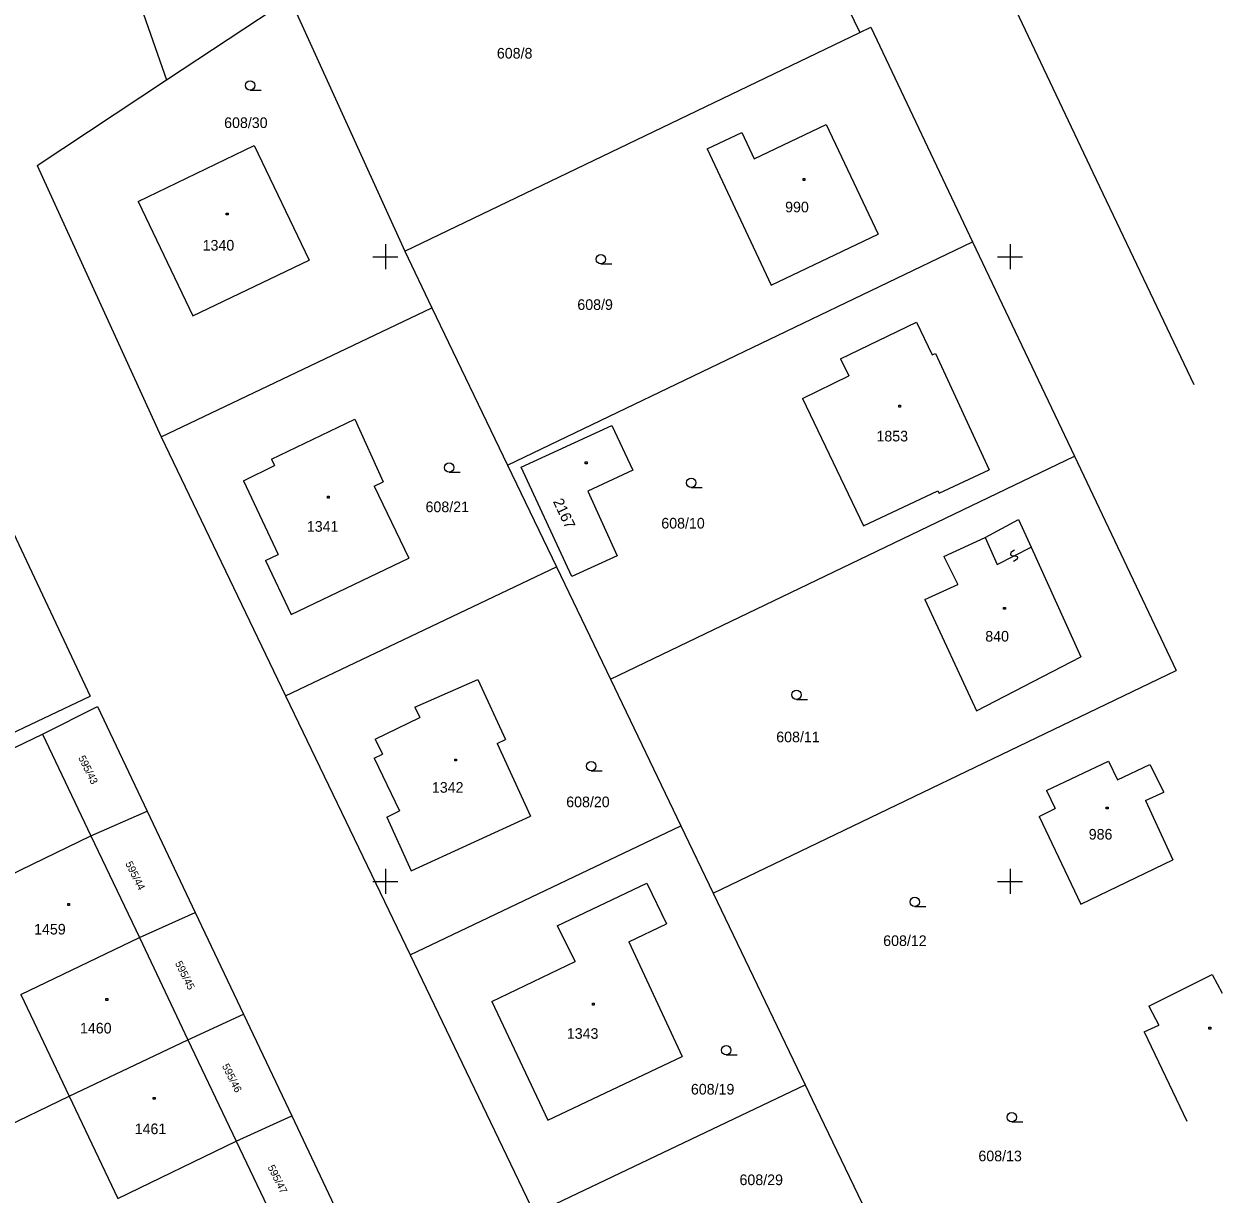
# Model space of a CAD drawing. Extents: x -493648 to -493033, y -1127718 to -1127026.
# Drawn here: x -493128.9 to -493033, y -1127275 to -1127181.4 of the extents above; entities that cross this region are included whole.
import ezdxf

# ---------------------------------------------------------------- set-up
doc = ezdxf.new("R2010")
doc.units = 0
doc.layers.add('katastrální mapa', color=7, linetype='Continuous')
doc.layers.add('síť', color=7, linetype='Continuous')

msp = doc.modelspace()

# ---------------------------------------------------------------- linework, layer by layer
at = {"layer": 'katastrální mapa'}
for p, q in [((-493063.68, -1127150.51), (-493043.37, -1127193.26)), ((-493073.86, -1127157.16), (-493062.04, -1127182.05)), ((-493117.52, -1127185.82), (-493107.66, -1127179.29)), ((-493107.66, -1127179.29), (-493098.45, -1127199.56)), ((-493119.75, -1127179.52), (-493117.52, -1127185.82)), ((-493098.45, -1127199.56), (-493062.04, -1127182.05)), ((-493062.04, -1127182.05), (-493061.14, -1127181.62)), ((-493061.14, -1127181.62), (-493053, -1127198.79)), ((-493127.87, -1127192.68), (-493117.52, -1127185.82)), ((-493110.83, -1127186.65), (-493109.95, -1127186.65)), ((-493070.48, -1127192.15), (-493064.72, -1127189.41)), ((-493064.72, -1127189.41), (-493060.57, -1127198.19)), ((-493074.24, -1127191.36), (-493071.48, -1127190.05)), ((-493071.48, -1127190.05), (-493070.48, -1127192.15)), ((-493119.79, -1127195.56), (-493110.5, -1127191.08)), ((-493110.5, -1127191.08), (-493106.11, -1127200.27)), ((-493074.24, -1127191.36), (-493069.14, -1127202.26)), ((-493127.87, -1127192.68), (-493117.94, -1127214.4)), ((-493066.57, -1127193.73), (-493066.42, -1127193.73)), ((-493066.57, -1127193.88), (-493066.57, -1127193.73)), ((-493066.42, -1127193.73), (-493066.42, -1127193.88)), ((-493043.37, -1127193.26), (-493035.31, -1127210.23)), ((-493066.42, -1127193.88), (-493066.57, -1127193.88)), ((-493119.79, -1127195.56), (-493115.41, -1127204.72)), ((-493112.75, -1127196.5), (-493112.6, -1127196.5)), ((-493112.75, -1127196.65), (-493112.75, -1127196.5)), ((-493112.6, -1127196.65), (-493112.75, -1127196.65)), ((-493112.6, -1127196.5), (-493112.6, -1127196.65)), ((-493069.14, -1127202.26), (-493060.57, -1127198.19)), ((-493098.45, -1127199.56), (-493096.28, -1127204.09)), ((-493090.22, -1127216.69), (-493053, -1127198.79)), ((-493053, -1127198.79), (-493044.86, -1127215.96)), ((-493115.41, -1127204.72), (-493106.11, -1127200.27)), ((-493082.76, -1127200.57), (-493081.88, -1127200.57)), ((-493117.94, -1127214.4), (-493096.28, -1127204.09)), ((-493096.28, -1127204.09), (-493090.22, -1127216.69)), ((-493063.58, -1127208.18), (-493057.5, -1127205.23)), ((-493057.5, -1127205.23), (-493056.23, -1127207.84)), ((-493063.58, -1127208.18), (-493062.92, -1127209.54)), ((-493056.23, -1127207.84), (-493055.98, -1127207.73)), ((-493055.98, -1127207.73), (-493051.67, -1127217.06)), ((-493066.61, -1127211.33), (-493062.92, -1127209.54)), ((-493066.61, -1127211.33), (-493061.74, -1127221.53)), ((-493058.92, -1127211.88), (-493058.77, -1127211.88)), ((-493058.92, -1127212.03), (-493058.92, -1127211.88)), ((-493058.77, -1127212.03), (-493058.92, -1127212.03)), ((-493058.77, -1127211.88), (-493058.77, -1127212.03)), ((-493109.11, -1127216.2), (-493102.45, -1127212.99)), ((-493102.45, -1127212.99), (-493100.17, -1127218.01)), ((-493133.79, -1127213.61), (-493123.64, -1127235.17)), ((-493089.13, -1127216.83), (-493081.89, -1127213.5)), ((-493081.89, -1127213.5), (-493080.2, -1127217.08)), ((-493117.94, -1127214.4), (-493107.99, -1127235.14)), ((-493111.35, -1127217.94), (-493108.88, -1127216.7)), ((-493109.11, -1127216.2), (-493108.88, -1127216.7)), ((-493090.22, -1127216.69), (-493086.32, -1127224.82)), ((-493085.07, -1127225.59), (-493089.13, -1127216.83)), ((-493084.01, -1127216.41), (-493083.86, -1127216.41)), ((-493084.01, -1127216.56), (-493084.01, -1127216.41)), ((-493083.86, -1127216.56), (-493084.01, -1127216.56)), ((-493083.86, -1127216.41), (-493083.86, -1127216.56)), ((-493082, -1127233.82), (-493044.86, -1127215.96)), ((-493044.86, -1127215.96), (-493036.72, -1127233.12)), ((-493094.9, -1127217.25), (-493094.02, -1127217.25)), ((-493080.2, -1127217.08), (-493083.79, -1127218.75)), ((-493055.69, -1127218.93), (-493051.67, -1127217.06)), ((-493111.35, -1127217.94), (-493108.58, -1127223.84)), ((-493100.89, -1127218.36), (-493100.17, -1127218.01)), ((-493100.89, -1127218.36), (-493098.13, -1127224.13)), ((-493083.79, -1127218.75), (-493081.44, -1127223.93)), ((-493075.52, -1127218.46), (-493074.64, -1127218.46)), ((-493061.74, -1127221.53), (-493055.78, -1127218.74)), ((-493055.78, -1127218.74), (-493055.69, -1127218.93)), ((-493104.65, -1127219.16), (-493104.5, -1127219.16)), ((-493104.65, -1127219.31), (-493104.65, -1127219.16)), ((-493104.5, -1127219.31), (-493104.65, -1127219.31)), ((-493104.5, -1127219.16), (-493104.5, -1127219.31)), ((-493051.99, -1127222.46), (-493049.34, -1127221.04)), ((-493049.34, -1127221.04), (-493048.33, -1127223.24)), ((-493055.3, -1127224), (-493051.99, -1127222.46)), ((-493051.99, -1127222.46), (-493051.05, -1127224.63)), ((-493051.05, -1127224.63), (-493048.33, -1127223.24)), ((-493049.65, -1127223.47), (-493049.94, -1127223.67)), ((-493048.33, -1127223.24), (-493044.33, -1127232.03)), ((-493109.61, -1127224.32), (-493108.58, -1127223.84)), ((-493109.61, -1127224.32), (-493107.55, -1127228.63)), ((-493107.55, -1127228.63), (-493098.13, -1127224.13)), ((-493081.44, -1127223.93), (-493085.07, -1127225.59)), ((-493055.3, -1127224), (-493054.18, -1127226.22)), ((-493049.94, -1127223.67), (-493049.98, -1127223.8)), ((-493049.98, -1127223.8), (-493049.94, -1127223.89)), ((-493049.94, -1127223.89), (-493049.8, -1127223.94)), ((-493049.8, -1127223.94), (-493049.58, -1127223.93)), ((-493049.44, -1127224.2), (-493049.73, -1127224.4)), ((-493049.58, -1127223.93), (-493049.44, -1127223.98)), ((-493049.44, -1127223.98), (-493049.4, -1127224.07)), ((-493049.4, -1127224.07), (-493049.44, -1127224.2)), ((-493107.99, -1127235.14), (-493086.32, -1127224.82)), ((-493086.32, -1127224.82), (-493082, -1127233.82)), ((-493056.84, -1127227.43), (-493054.18, -1127226.22)), ((-493056.84, -1127227.43), (-493052.69, -1127236.34)), ((-493050.52, -1127228.06), (-493050.37, -1127228.06)), ((-493050.52, -1127228.21), (-493050.52, -1127228.06)), ((-493050.37, -1127228.21), (-493050.52, -1127228.21)), ((-493050.37, -1127228.06), (-493050.37, -1127228.21)), ((-493052.69, -1127236.34), (-493044.33, -1127232.03)), ((-493073.78, -1127250.94), (-493036.72, -1127233.12)), ((-493097.66, -1127236.04), (-493092.6, -1127233.83)), ((-493092.6, -1127233.83), (-493090.39, -1127238.65)), ((-493082, -1127233.82), (-493076.37, -1127245.55)), ((-493131.12, -1127238.72), (-493123.64, -1127235.17)), ((-493127.44, -1127238.2), (-493123.05, -1127236.01)), ((-493123.05, -1127236.01), (-493119.08, -1127244.37)), ((-493107.99, -1127235.14), (-493098.03, -1127255.87)), ((-493067.1, -1127235.43), (-493066.22, -1127235.43)), ((-493100.82, -1127238.6), (-493097.25, -1127236.89)), ((-493097.66, -1127236.04), (-493097.25, -1127236.89)), ((-493131.56, -1127240.19), (-493127.44, -1127238.2)), ((-493127.44, -1127238.2), (-493123.57, -1127246.34)), ((-493100.82, -1127238.6), (-493100.24, -1127239.8)), ((-493091.05, -1127238.95), (-493090.39, -1127238.65)), ((-493100.91, -1127240.14), (-493100.24, -1127239.8)), ((-493091.05, -1127238.95), (-493088.38, -1127244.77)), ((-493100.91, -1127240.14), (-493098.88, -1127244.36)), ((-493094.45, -1127240.2), (-493094.3, -1127240.2)), ((-493094.45, -1127240.35), (-493094.45, -1127240.2)), ((-493094.3, -1127240.35), (-493094.45, -1127240.35)), ((-493094.3, -1127240.2), (-493094.3, -1127240.35)), ((-493047.09, -1127242.73), (-493042.13, -1127240.37)), ((-493042.13, -1127240.37), (-493041.41, -1127241.86)), ((-493041.41, -1127241.86), (-493038.83, -1127240.63)), ((-493038.83, -1127240.63), (-493037.7, -1127242.85)), ((-493083.53, -1127241.14), (-493082.65, -1127241.14)), ((-493047.09, -1127242.73), (-493046.4, -1127244.17)), ((-493039.16, -1127243.53), (-493037.7, -1127242.85)), ((-493039.16, -1127243.53), (-493036.97, -1127248.28)), ((-493123.57, -1127246.34), (-493119.08, -1127244.37)), ((-493119.08, -1127244.37), (-493115.22, -1127252.5)), ((-493099.89, -1127244.85), (-493098.88, -1127244.36)), ((-493047.69, -1127244.79), (-493046.4, -1127244.17)), ((-493042.31, -1127244.05), (-493042.16, -1127244.05)), ((-493042.31, -1127244.2), (-493042.31, -1127244.05)), ((-493042.16, -1127244.2), (-493042.31, -1127244.2)), ((-493042.16, -1127244.05), (-493042.16, -1127244.2)), ((-493099.89, -1127244.85), (-493097.93, -1127249.14)), ((-493098.03, -1127255.87), (-493076.37, -1127245.55)), ((-493097.93, -1127249.14), (-493088.38, -1127244.77)), ((-493076.37, -1127245.55), (-493073.78, -1127250.94)), ((-493047.69, -1127244.79), (-493044.33, -1127251.81)), ((-493133.05, -1127250.93), (-493123.57, -1127246.34)), ((-493123.57, -1127246.34), (-493119.69, -1127254.49)), ((-493044.33, -1127251.81), (-493036.97, -1127248.28)), ((-493086.26, -1127253.56), (-493079.07, -1127250.13)), ((-493079.07, -1127250.13), (-493077.5, -1127253.4)), ((-493073.78, -1127250.94), (-493066.41, -1127266.29)), ((-493125.43, -1127251.77), (-493125.28, -1127251.77)), ((-493125.43, -1127251.92), (-493125.43, -1127251.77)), ((-493125.28, -1127251.92), (-493125.43, -1127251.92)), ((-493125.28, -1127251.77), (-493125.28, -1127251.92)), ((-493057.63, -1127252.01), (-493056.75, -1127252.01)), ((-493119.69, -1127254.49), (-493115.22, -1127252.5)), ((-493115.22, -1127252.5), (-493111.36, -1127260.63)), ((-493086.26, -1127253.56), (-493084.82, -1127256.42)), ((-493080.53, -1127254.84), (-493077.5, -1127253.4)), ((-493129.18, -1127259.06), (-493119.69, -1127254.49)), ((-493119.69, -1127254.49), (-493115.81, -1127262.67)), ((-493080.53, -1127254.84), (-493076.25, -1127264.02)), ((-493098.03, -1127255.87), (-493088.08, -1127276.6)), ((-493091.49, -1127259.61), (-493084.82, -1127256.42)), ((-493038.9, -1127259.99), (-493033.84, -1127257.45)), ((-493033.84, -1127257.45), (-493033.04, -1127258.95)), ((-493129.18, -1127259.06), (-493125.31, -1127267.2)), ((-493122.38, -1127259.38), (-493122.23, -1127259.38)), ((-493122.38, -1127259.53), (-493122.38, -1127259.38)), ((-493122.23, -1127259.53), (-493122.38, -1127259.53)), ((-493122.23, -1127259.38), (-493122.23, -1127259.53)), ((-493091.49, -1127259.61), (-493087.01, -1127269.1)), ((-493083.44, -1127259.75), (-493083.29, -1127259.75)), ((-493083.44, -1127259.9), (-493083.44, -1127259.75)), ((-493083.29, -1127259.9), (-493083.44, -1127259.9)), ((-493083.29, -1127259.75), (-493083.29, -1127259.9)), ((-493038.9, -1127259.99), (-493038.11, -1127261.5)), ((-493115.81, -1127262.67), (-493111.36, -1127260.63)), ((-493111.36, -1127260.63), (-493107.5, -1127268.76)), ((-493039.27, -1127262.05), (-493038.11, -1127261.5)), ((-493034.09, -1127261.67), (-493033.94, -1127261.67)), ((-493034.09, -1127261.82), (-493034.09, -1127261.67)), ((-493033.94, -1127261.82), (-493034.09, -1127261.82)), ((-493033.94, -1127261.67), (-493033.94, -1127261.82)), ((-493125.31, -1127267.2), (-493115.81, -1127262.67)), ((-493115.81, -1127262.67), (-493111.94, -1127270.8)), ((-493039.27, -1127262.05), (-493035.86, -1127269.18)), ((-493087.01, -1127269.1), (-493076.25, -1127264.02)), ((-493072.72, -1127263.89), (-493071.84, -1127263.89)), ((-493088.08, -1127276.6), (-493066.41, -1127266.29)), ((-493066.41, -1127266.29), (-493065.55, -1127268.07)), ((-493141.46, -1127274.93), (-493125.31, -1127267.2)), ((-493125.31, -1127267.2), (-493121.43, -1127275.37)), ((-493118.58, -1127267.29), (-493118.43, -1127267.29)), ((-493118.58, -1127267.44), (-493118.58, -1127267.29)), ((-493118.43, -1127267.44), (-493118.58, -1127267.44)), ((-493118.43, -1127267.29), (-493118.43, -1127267.44)), ((-493065.55, -1127268.07), (-493057.33, -1127285.2)), ((-493111.94, -1127270.8), (-493107.5, -1127268.76)), ((-493107.5, -1127268.76), (-493103.64, -1127276.89)), ((-493049.87, -1127269.25), (-493048.99, -1127269.25)), ((-493121.43, -1127275.37), (-493111.94, -1127270.8)), ((-493111.94, -1127270.8), (-493108.07, -1127278.94))]:
    msp.add_line(p, q, dxfattribs=at)
for centre in [(-493110.83, -1127186.275), (-493082.76, -1127200.195), (-493094.9, -1127216.875), (-493075.52, -1127218.085), (-493067.1, -1127235.055), (-493083.53, -1127240.765), (-493057.63, -1127251.635), (-493072.72, -1127263.515), (-493049.87, -1127268.875)]:
    msp.add_circle(centre, 0.375, dxfattribs=at)
at = {"layer": 'síť'}
for p, q in [((-493100, -1127199), (-493100, -1127201)), ((-493050, -1127199), (-493050, -1127201)), ((-493101, -1127200), (-493099, -1127200)), ((-493051, -1127200), (-493049, -1127200)), ((-493100, -1127249), (-493100, -1127251)), ((-493050, -1127249), (-493050, -1127251)), ((-493101, -1127250), (-493099, -1127250)), ((-493051, -1127250), (-493049, -1127250))]:
    msp.add_line(p, q, dxfattribs=at)

# ---------------------------------------------------------------- texts
at = {"layer": 'katastrální mapa'}
for s, p in [('608/8', (-493091.08, -1127184.13)), ('608/30', (-493112.91, -1127189.69)), ('990', (-493068.01, -1127196.44)), ('1340', (-493114.63, -1127199.5)), ('608/9', (-493084.64, -1127204.25)), ('1853', (-493060.7, -1127214.78)), ('608/21', (-493096.79, -1127220.44)), ('1341', (-493106.29, -1127222.01)), ('608/10', (-493077.92, -1127221.75)), ('840', (-493051.99, -1127230.8)), ('608/11', (-493068.72, -1127238.86)), ('1342', (-493096.28, -1127242.9)), ('608/20', (-493085.53, -1127244.06)), ('986', (-493043.71, -1127246.65)), ('1459', (-493128.12, -1127254.25)), ('608/12', (-493060.16, -1127255.17)), ('1460', (-493124.45, -1127262.17)), ('1343', (-493085.48, -1127262.6)), ('608/19', (-493075.55, -1127267.06)), ('1461', (-493120.07, -1127270.23)), ('608/13', (-493052.54, -1127272.4)), ('608/29', (-493071.66, -1127274.31))]:
    msp.add_text(s, height=0.849996, dxfattribs=at).set_placement(p)
for s, height, rotation, p in [('2167', 0.849996, 295.1999972, (-493086.61, -1127219.58)), ('595/43', 0.599994, 296.559, (-493124.61, -1127240.1)), ('595/44', 0.599994, 296.559, (-493120.84, -1127248.57)), ('595/45', 0.599994, 296.559, (-493116.86, -1127256.55)), ('595/46', 0.599994, 296.559, (-493113.1, -1127264.77)), ('595/47', 0.599994, 296.559, (-493109.45, -1127272.87))]:
    msp.add_text(s, height=height, rotation=rotation, dxfattribs=at).set_placement(p)

doc.saveas('drawing.dxf')
